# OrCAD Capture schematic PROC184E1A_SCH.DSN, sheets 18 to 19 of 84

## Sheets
18 18. SOC MCU & MAIN GEN IO, OSC: size C; title: SOC MCU & MAIN GENERAL; company: TEXAS INSTRUMENTS INCORPORATED; note: PROC184_SCH
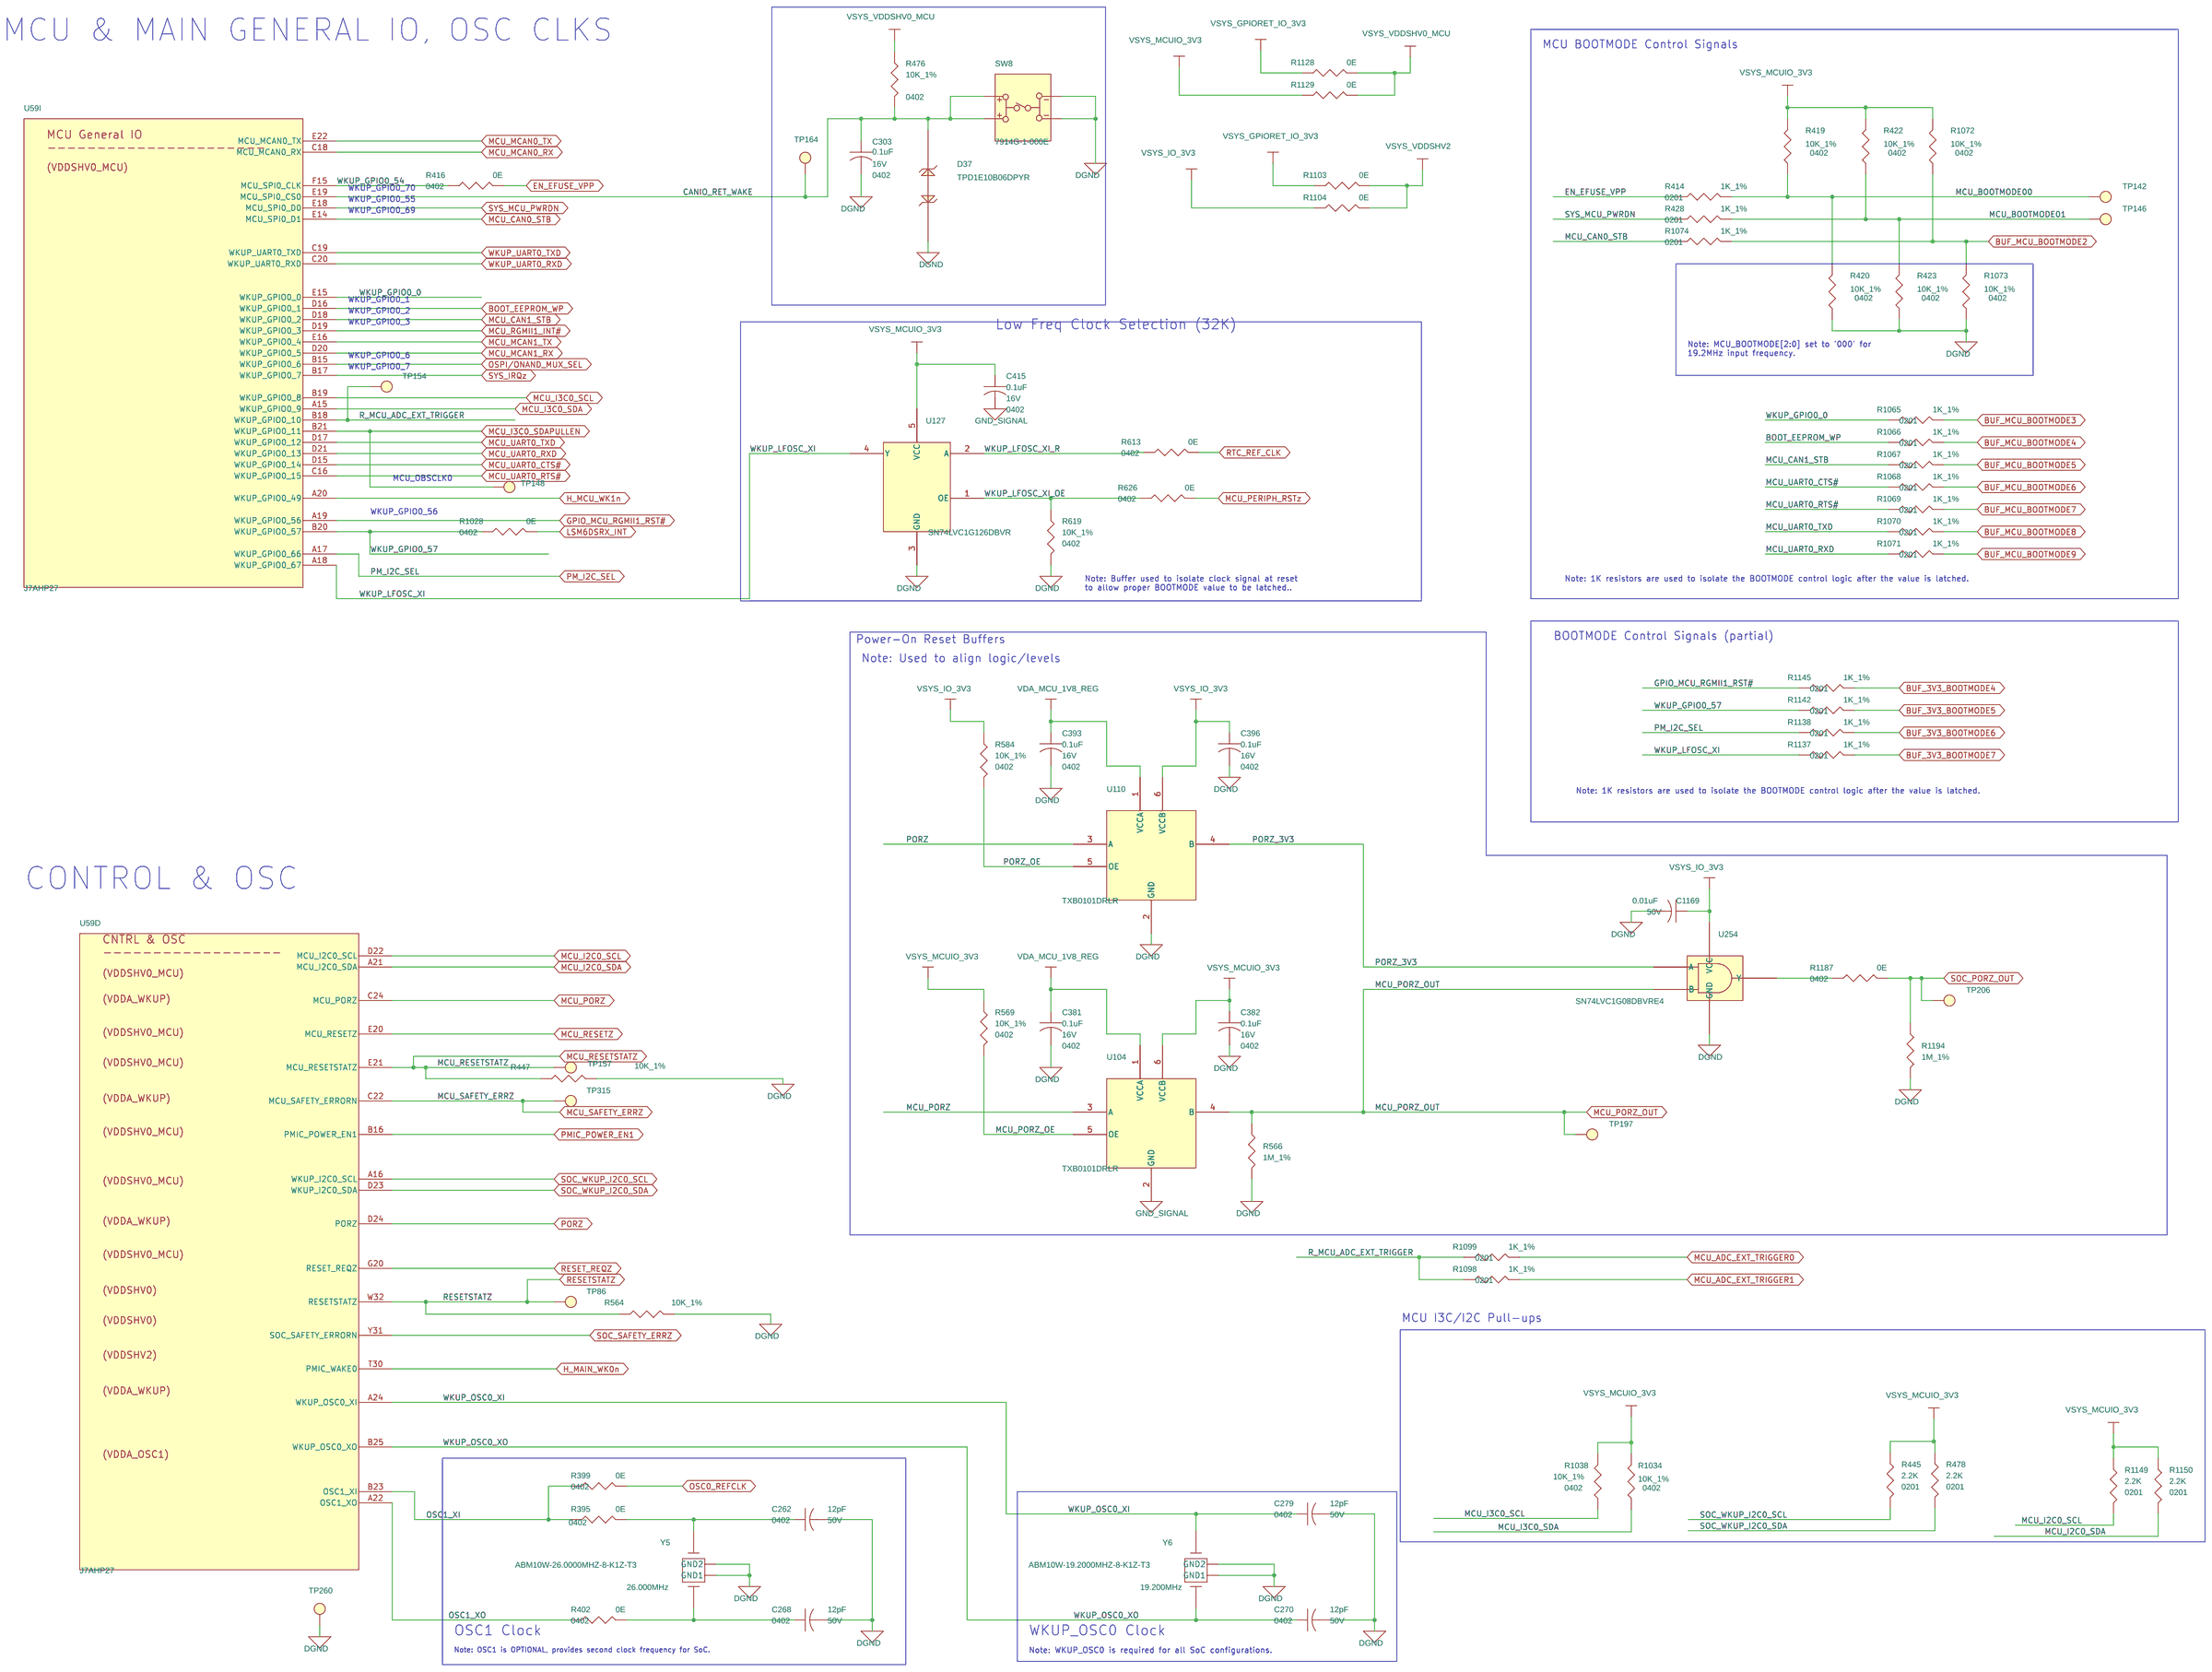
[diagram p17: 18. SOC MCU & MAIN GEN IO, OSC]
19 19. GENERAL: size C; title: GENERAL IO; company: TEXAS INSTRUMENTS INCORPORATED; note: PROC184_SCH
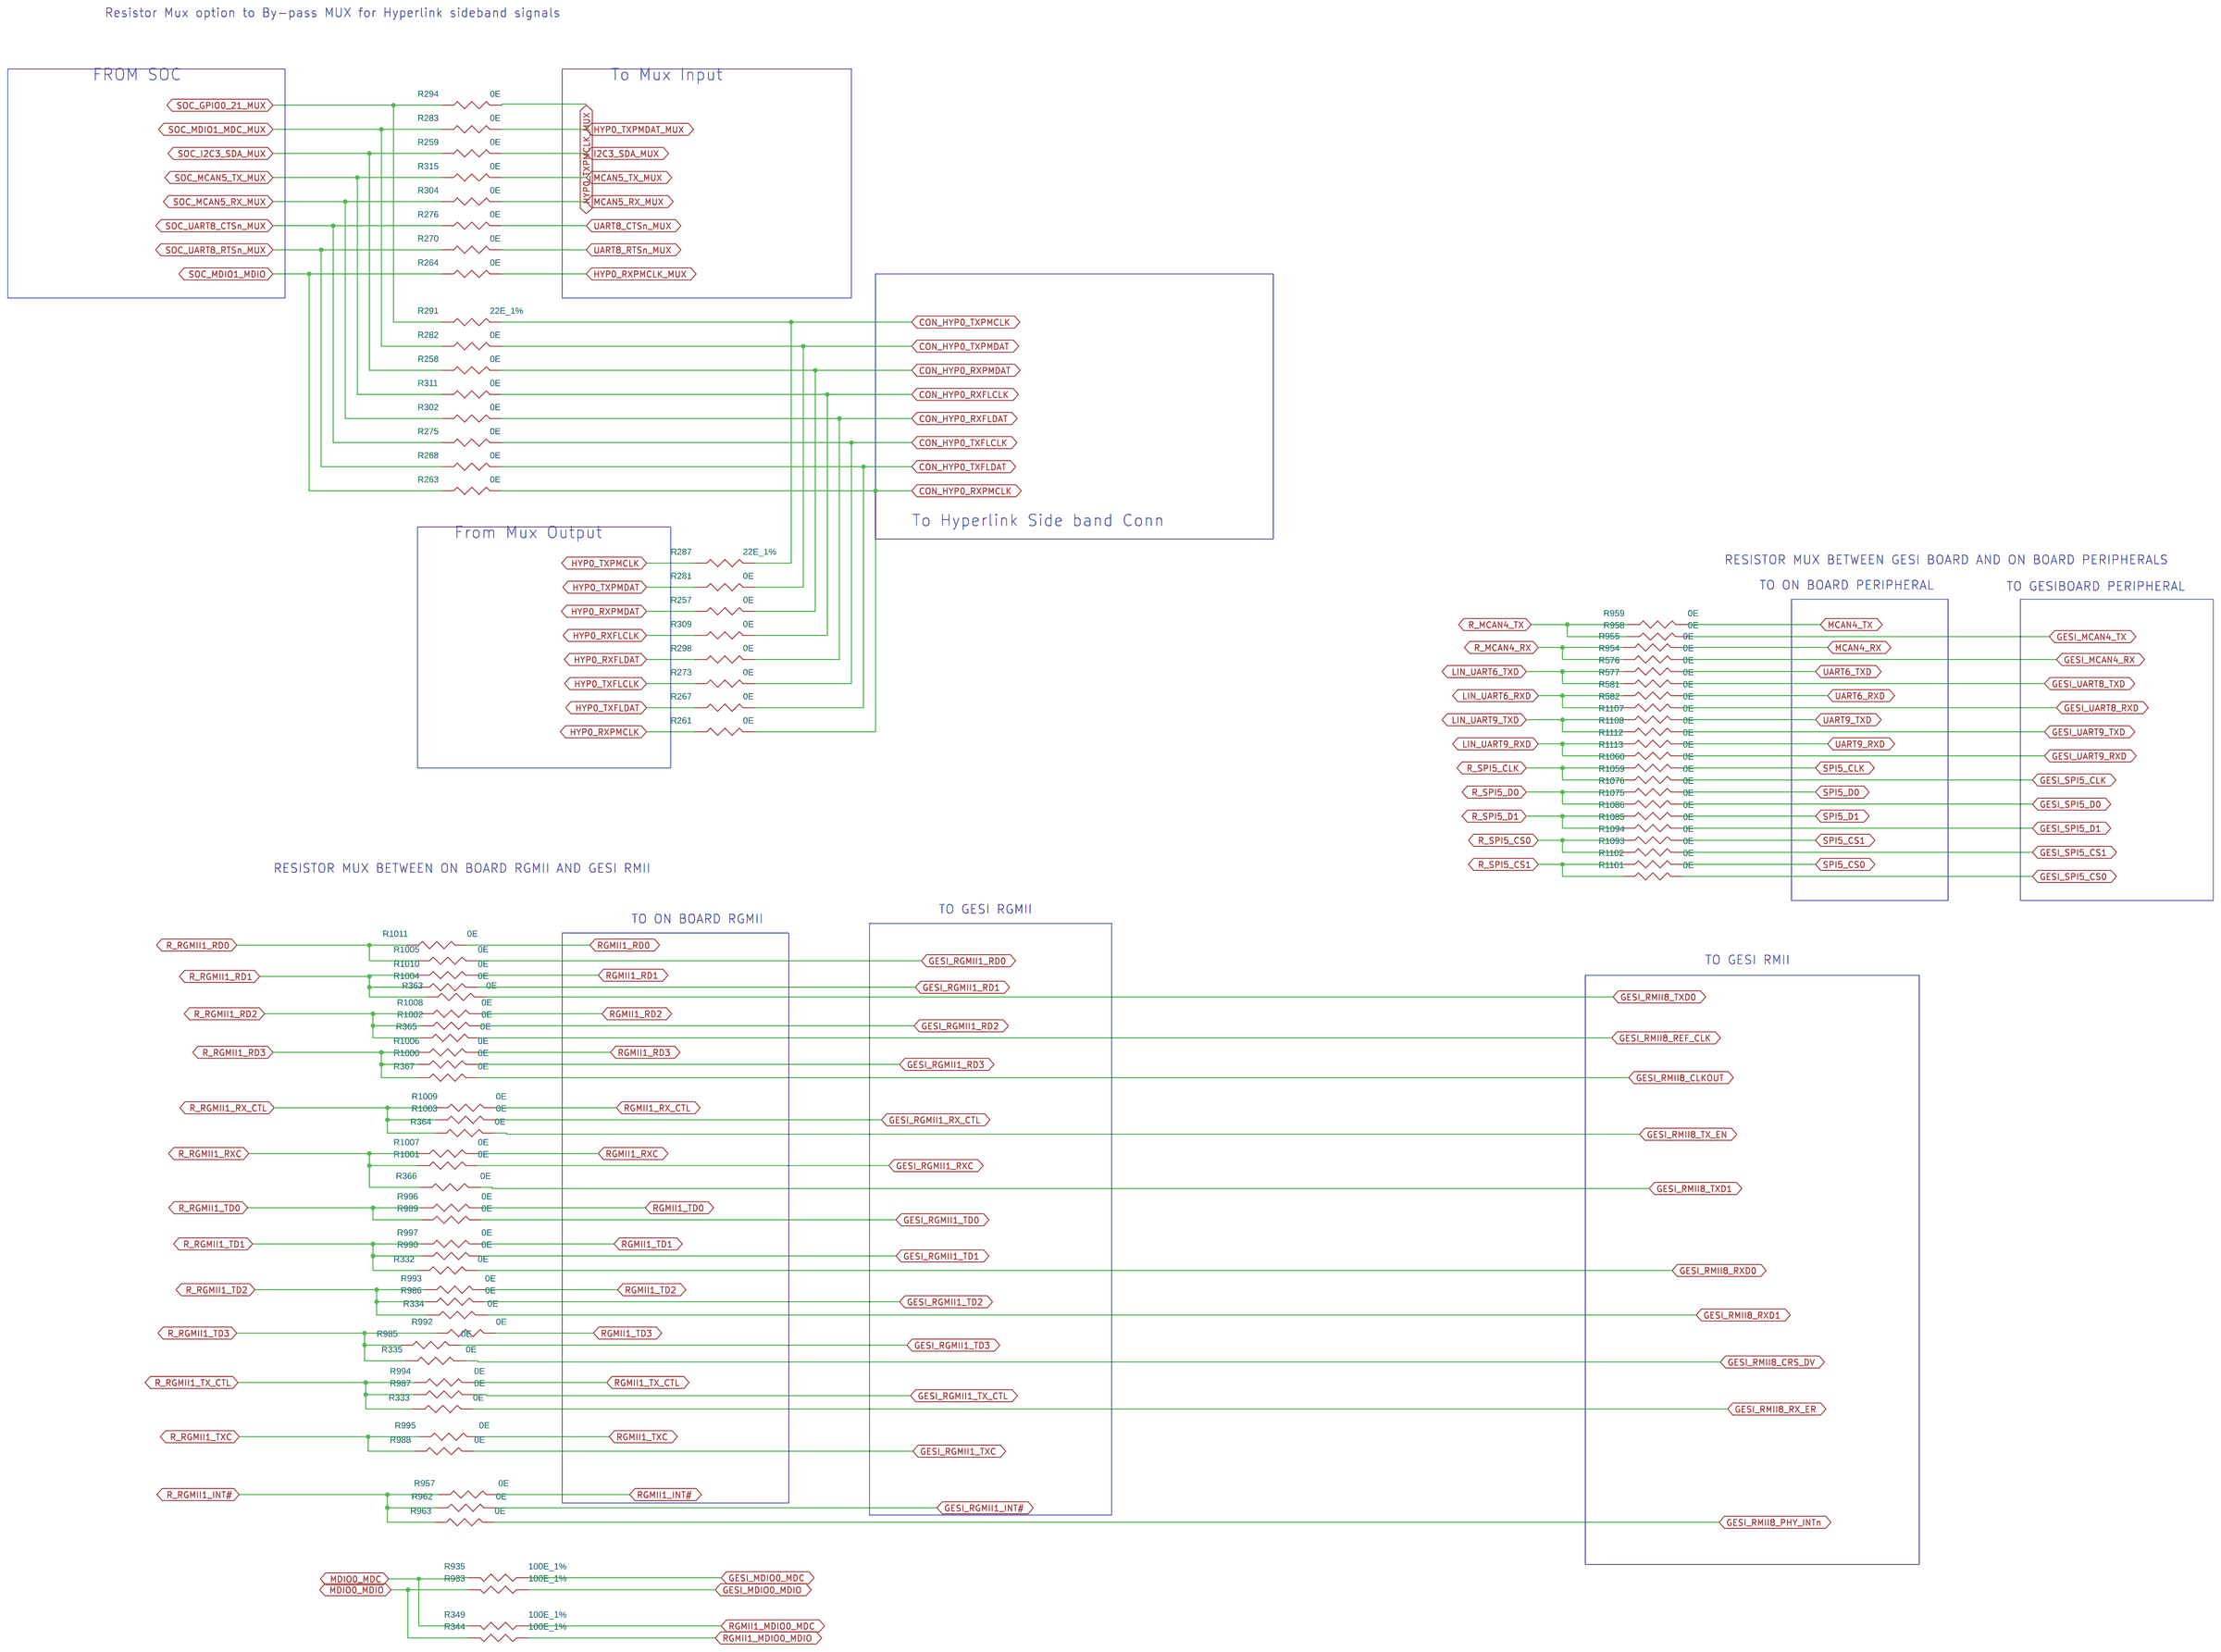
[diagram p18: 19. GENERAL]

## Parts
sheet 15. SOC EMIF1 & LPDDR4
U59  J7AHP27  [BGASKT-33X33-1063-P8MM]  (sections A,B,C,D,E,F,G,H,I,J,K,L,M,N,O,P,Q,R,S,T,U,V,W)
sheet 18. SOC MCU & MAIN GEN IO, OSC
C262  12pF  [CAP0402_0-75]
C268  12pF  [CAP0402_0-75]
C270  12pF  [CAP0402_0-75]
C279  12pF  [CAP0402_0-75]
C303  0.1uF  [CAP0402_0-75]
C381  0.1uF  [CAP0402_0-75]
C382  0.1uF  [CAP0402_0-75]
C393  0.1uF  [CAP0402_0-75]
C396  0.1uF  [CAP0402_0-75]
C415  0.1uF  [CAP0402_0-75]
C1169  0.01uF  [CAP0402_0-75]
D37  TPD1E10B06DPYR  [DIO_DFN0402_0-5]
R395  0E  [RES0402_0-5]
R399  0E  [RES0402_0-5]
R402  0E  [RES0402_0-5]
R414  1K_1%  [RES0201_0-5]
R416  0E  [RES0402_0-5]
R419  10K_1%  [RES0402_0-5]
R420  10K_1%  [RES0402_0-5]
R422  10K_1%  [RES0402_0-5]
R423  10K_1%  [RES0402_0-5]
R428  1K_1%  [RES0201_0-5]
R445  2.2K  [RES0201_0-5]
R447  10K_1%  [RES0402_0-5]
R476  10K_1%  [RES0402_0-5]
R478  2.2K  [RES0201_0-5]
R564  10K_1%  [RES0402_0-5]
R566  1M_1%  [RES0402_0-5]
R569  10K_1%  [RES0402_0-5]
R584  10K_1%  [RES0402_0-5]
R613  0E  [RES0402_0-5]
R619  10K_1%  [RES0402_0-5]
R626  0E  [RES0402_0-5]
R1028  0E  [RES0402_0-5]
R1034  10K_1%  [RES0402_0-5]
R1038  10K_1%  [RES0402_0-5]
R1065  1K_1%  [RES0201_0-5]
R1066  1K_1%  [RES0201_0-5]
R1067  1K_1%  [RES0201_0-5]
R1068  1K_1%  [RES0201_0-5]
R1069  1K_1%  [RES0201_0-5]
R1070  1K_1%  [RES0201_0-5]
R1071  1K_1%  [RES0201_0-5]
R1072  10K_1%  [RES0402_0-5]
R1073  10K_1%  [RES0402_0-5]
R1074  1K_1%  [RES0201_0-5]
R1098  1K_1%  [RES0201_0-5]
R1099  1K_1%  [RES0201_0-5]
R1103  0E  [RES0402_0-5]
R1104  0E  [RES0402_0-5]
R1128  0E  [RES0402_0-5]
R1129  0E  [RES0402_0-5]
R1137  1K_1%  [RES0201_0-5]
R1138  1K_1%  [RES0201_0-5]
R1142  1K_1%  [RES0201_0-5]
R1145  1K_1%  [RES0201_0-5]
R1149  2.2K  [RES0201_0-5]
R1150  2.2K  [RES0201_0-5]
R1187  0E  [RES0402_0-5]
R1194  1M_1%  [RES0402_0-5]
SW8  7914G-1-000E  [SW4_100X216_200X200_SMD_4-2]
TP86  TP30_SMD  [TP30_SMD]
TP142  TP30_SMD  [TP30_SMD]
TP146  TP30_SMD  [TP30_SMD]
TP148  TP30_SMD  [TP30_SMD]
TP154  TP30_SMD  [TP30_SMD]
TP157  TP30_SMD  [TP30_SMD]
TP164  TP30_SMD  [TP30_SMD]
TP197  TP30_SMD  [TP30_SMD]
TP206  TP30_SMD  [TP30_SMD]
TP260  TP30_SMD  [TP30_SMD]
TP315  TP30_SMD  [TP30_SMD]
U104  TXB0101DRLR  [SOT563-6_0-6]
U110  TXB0101DRLR  [SOT563-6_0-6]
U127  SN74LVC1G126DBVR  [SOT23-5_1-5]
U254  SN74LVC1G08DBVRE4  [SOT23-5]
Y5  26.000MHz  [XTAL4_ABM10W_100X80_SMD_0-6]
Y6  19.200MHz  [XTAL4_ABM10W_100X80_SMD_0-6]
sheet 19. GENERAL
R257  0E  [RES0201_0-5]
R258  0E  [RES0201_0-5]
R259  0E  [RES0201_0-5]
R261  0E  [RES0201_0-5]
R263  0E  [RES0201_0-5]
R264  0E  [RES0201_0-5]
R267  0E  [RES0201_0-5]
R268  0E  [RES0201_0-5]
R270  0E  [RES0201_0-5]
R273  0E  [RES0201_0-5]
R275  0E  [RES0201_0-5]
R276  0E  [RES0201_0-5]
R281  0E  [RES0201_0-5]
R282  0E  [RES0201_0-5]
R283  0E  [RES0201_0-5]
R287  22E_1%  [RES0402_0-5]
R291  22E_1%  [RES0402_0-5]
R294  0E  [RES0201_0-5]
R298  0E  [RES0201_0-5]
R302  0E  [RES0201_0-5]
R304  0E  [RES0201_0-5]
R309  0E  [RES0201_0-5]
R311  0E  [RES0201_0-5]
R315  0E  [RES0201_0-5]
R332  0E  [RES0201_0-5]
R333  0E  [RES0201_0-5]
R334  0E  [RES0201_0-5]
R335  0E  [RES0201_0-5]
R344  100E_1%  [RES0402_0-5]
R349  100E_1%  [RES0402_0-5]
R363  0E  [RES0201_0-5]
R364  0E  [RES0201_0-5]
R365  0E  [RES0201_0-5]
R366  0E  [RES0201_0-5]
R367  0E  [RES0201_0-5]
R576  0E  [RES0402_0-5]
R577  0E  [RES0402_0-5]
R581  0E  [RES0402_0-5]
R582  0E  [RES0402_0-5]
R933  100E_1%  [RES0402_0-5]
R935  100E_1%  [RES0402_0-5]
R954  0E  [RES0402_0-5]
R955  0E  [RES0402_0-5]
R957  0E  [RES0201_0-5]
R958  0E  [RES0402_0-5]
R959  0E  [RES0402_0-5]
R962  0E  [RES0201_0-5]
R963  0E  [RES0201_0-5]
R985  0E  [RES0201_0-5]
R986  0E  [RES0201_0-5]
R987  0E  [RES0201_0-5]
R988  0E  [RES0201_0-5]
R989  0E  [RES0201_0-5]
R990  0E  [RES0201_0-5]
R992  0E  [RES0201_0-5]
R993  0E  [RES0201_0-5]
R994  0E  [RES0201_0-5]
R995  0E  [RES0201_0-5]
R996  0E  [RES0201_0-5]
R997  0E  [RES0201_0-5]
R1000  0E  [RES0201_0-5]
R1001  0E  [RES0201_0-5]
R1002  0E  [RES0201_0-5]
R1003  0E  [RES0201_0-5]
R1004  0E  [RES0201_0-5]
R1005  0E  [RES0201_0-5]
R1006  0E  [RES0201_0-5]
R1007  0E  [RES0201_0-5]
R1008  0E  [RES0201_0-5]
R1009  0E  [RES0201_0-5]
R1010  0E  [RES0201_0-5]
R1011  0E  [RES0201_0-5]
R1059  0E  [RES0402_0-5]
R1060  0E  [RES0402_0-5]
R1075  0E  [RES0402_0-5]
R1076  0E  [RES0402_0-5]
R1085  0E  [RES0402_0-5]
R1086  0E  [RES0402_0-5]
R1093  0E  [RES0402_0-5]
R1094  0E  [RES0402_0-5]
R1101  0E  [RES0402_0-5]
R1102  0E  [RES0402_0-5]
R1107  0E  [RES0402_0-5]
R1108  0E  [RES0402_0-5]
R1112  0E  [RES0402_0-5]
R1113  0E  [RES0402_0-5]

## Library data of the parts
U59 = J7AHP27SoC_BGA1063: IC J7AHP27 SoC EVM MICROPROCESSOR BGA1063; Chkd/date: PRADEEP/181223; Crtd /date: TAMILARASU/111223; Custom_Duty: 15%; Customs_HS_Code: 85423100; Distributor_name: NA; Distributor_part_number: NA; Footprint Path: Y:\MIS_DATABASE\Library\ALTIUM_TOOL\PCB_FOOTPRINTS\Altium_Footprint_Lib.PcbLib; Height: 3.30MM; Library Path: Y:\MIS_DATABASE\Library\ALTIUM_TOOL\SCHEMATICS_PARTS\MS_MICROPROCESSOR_Library.schlib; Mfr_name: NA; Mistral Part No: 141223120002; Package: BGA1063; Part_type: ICS\DIGITAL\MICROPROCESSOR; Project: J7AHP27_V08 SOC; RoHS: NA; Temperature: NA; Tolerance: NA; Voltage: NA; Wattage: NA; Weight: NA; Datasheet: Y:\MIS_DATABASE\DATASHEETS\ICS\DIGITAL\MICROCONTROLLER\J7AHP27.PDF
C262 C268 C270 C279 = CAP: CAP CERAMIC 12pF 50V 5% C0G(NP0) 0402; Automotive Alternate_mfr_name: TDK; Automotive Alternate_mfr_part_number: CGA2B2C0G1H120J050BA; Chkd/date: SHREESHAIL/281105; Crtd /date: MAZHAR/040505; Custom_Duty: 15%; Customs_HS_Code: 85322990; Direct Alternate_mfr_name: SAMSUNG; Direct Alternate_mfr_part_number: CL05C120JB5NNNC; Distributor_name: DIGIKEY; Distributor_part_number: 478-1071-1-ND; Footprint Path: Y:\MIS_DATABASE\Library\ALTIUM_TOOL\PCB_FOOTPRINTS\Altium_Footprint_Lib.PcbLib; Height: 0.56MM; Library Path: Y:\MIS_DATABASE\Library\ALTIUM_TOOL\SCHEMATICS_PARTS\MS_DISCRETE_Library.schlib; Manufacturer: AVX CORPORATION; Mfr_name: AVX CORPORATION; Mfr_part_number: 04025A120JAT2A; Mistral Part No: 120015110024-R; Package: 0402; Part_type: CAPACITORS\CERAMIC; Project: EPDA_CORE; RoHS: RoHS; Temperature: -55°C+125°C; Tolerance: 5%; Voltage: 50V; Wattage: NA; Weight: 0.65mg; Datasheet: Y:\MIS_DATABASE\DATASHEETS\CAPACITORS\AVX_MLC.PDF
C303 C381 C382 C393 C396 C415 = CAP: CAP CERAMIC 0.1uF 16V 10% X7R AUTO 0402; Automotive Alternate_mfr_name: TDK; Automotive Alternate_mfr_part_number: CGA2B1X7R1C104K050BC; Chkd/date: NAVEED/021014; Crtd /date: VASANTHA/300514; Custom_Duty: 15%; Customs_HS_Code: 85322990; Direct Alternate_mfr_name: MURATA; Direct Alternate_mfr_part_number: GCM155R71C104JA55D; Distributor_name: DIGIKEY; Distributor_part_number: 490-4759-1-ND; Footprint Path: Y:\MIS_DATABASE\Library\ALTIUM_TOOL\PCB_FOOTPRINTS\Altium_Footprint_Lib.PcbLib; Height: 0.55MM; Library Path: Y:\MIS_DATABASE\Library\ALTIUM_TOOL\SCHEMATICS_PARTS\MS_DISCRETE_Library.schlib; Manufacturer: MURATA; Mfr_name: MURATA; Mfr_part_number: GCM155R71C104KA55D; Mistral Part No: 120016070006-R; Package: 0402; Part_type: CAPACITORS\CERAMIC; Project: DCMIST_FPGA_CARD; RoHS: RoHS; Temperature: -55°C+125°C; Tolerance: 10%; Voltage: 16V; Wattage: NA; Weight: 6mg; Datasheet: Y:\MIS_DATABASE\DATASHEETS\CAPACITORS\MURATA-GCM-SER.PDF
C1169 = CAP: CAP CERAMIC 0.01uF 50V 10% X7R 0402; Automotive Alternate_mfr_name: TDK; Automotive Alternate_mfr_part_number: CGA2B3X7R1H103K050BB; Chkd/date: MANIRAJA/280319; Crtd /date: MANIRAJA/280319; Custom_Duty: 15%; Customs_HS_Code: 85322990; Direct Alternate_mfr_name: TDK; Direct Alternate_mfr_part_number: C1005X7R1H103K050BE; Distributor_name: DIGIKEY; Distributor_part_number: 490-4516-1-ND; Footprint Path: Y:\MIS_DATABASE\Library\ALTIUM_TOOL\PCB_FOOTPRINTS\Altium_Footprint_Lib.PcbLib; Height: 0.55MM; Library Path: Y:\MIS_DATABASE\Library\ALTIUM_TOOL\SCHEMATICS_PARTS\MS_DISCRETE_Library.schlib; Manufacturer: MURATA; Mfr_name: MURATA; Mfr_part_number: GRM155R71H103KA88D; Mistral Part No: 120009030025-R; Package: 0402; Part_type: CAPACITORS\CERAMIC; Project: G4_SVGA; RoHS: RoHS; Temperature: -55°C+125°C; Tolerance: 10%; Voltage: 50V; Wattage: NA; Weight: 0.65mg; Datasheet: Y:\MIS_DATABASE\DATASHEETS\CAPACITORS\GRM155R71H103KA88D.PDF
D37 = DIODE_SOD323: DIODE 1CH ESD PROTECTION X1SON2; Chkd/date: MANIRAJA/040420; Crtd /date: VASANTHA/181114; Custom_Duty: 15%; Customs_HS_Code: 85423100; Distributor_name: DIGIKEY; Distributor_part_number: 296-30406-1-ND; Footprint Path: Y:\MIS_DATABASE\Library\ALTIUM_TOOL\PCB_FOOTPRINTS\Altium_Footprint_Lib.PcbLib; Height: 0.45MM; Library Path: Y:\MIS_DATABASE\Library\ALTIUM_TOOL\SCHEMATICS_PARTS\MS_DISCRETE_Library.schlib; Manufacturer: TEXAS INSTRUMENTS; Mfr_name: TEXAS INSTRUMENTS; Mistral Part No: 130014110022-R; Package: X1SON2; Part_type: DIODE; Project: GALILEO_EVM; RoHS: RoHS; Temperature: -40°C+125°C; Tolerance: NA; Voltage: NA; Wattage: NA; Weight: 1mg; Datasheet: Y:\MIS_DATABASE\DATASHEETS\ICS\INTERFACE\TPD1E10B06-SER.PDF
R395 R399 R402 R576 R577 R581 R582 R626 R954 R955 R958 R959 R1028 R1059 R1060 R1075 R1076 R1085 R1086 R1093 R1094 R1101-R1104 R1107 R1108 R1112 R1113 R1128 R1129 = RESISTOR: RES 0E 1/10W JUMPER 0402; Chkd/date: VASANTHA/061216; Crtd /date: NAVEED/201014; Custom_Duty: 15%; Customs_HS_Code: 85332119; Distributor_name: DIGIKEY; Distributor_part_number: P0.0JCT-ND; Footprint Path: Y:\MIS_DATABASE\Library\ALTIUM_TOOL\PCB_FOOTPRINTS\Altium_Footprint_Lib.PcbLib; Height: 0.40MM; IBISSP_MODLES: VALUE REPEATING 2 TIME; Library Path: Y:\MIS_DATABASE\Library\ALTIUM_TOOL\SCHEMATICS_PARTS\MS_DISCRETE_Library.schlib; Manufacturer: PANASONIC-ECG; Mfr_name: PANASONIC-ECG; Mfr_part_number: ERJ-2GE0R00X; Mistral Part No: 110018030052-R; Package: 0402; Part_type: RESISTORS\FIXED; Project: AEGIS POM; RoHS: RoHS; Temperature: -55°C+155°C; Tolerance: NA; Voltage: NA; Wattage: 1/10W; Weight: 0.8mg; Datasheet: Y:\MIS_DATABASE\DATASHEETS\RESISTORS\PAN-ERJSER_NOV17.PDF
R414 R428 R1065-R1071 R1074 R1098 R1099 R1137 R1138 R1142 R1145 = RESISTOR: RES 1K 1/20W 1% 0201; Chkd/date: RAGESH/120511; Crtd /date: MAZHAR/100511; Custom_Duty: 15%; Customs_HS_Code: 85332119; Distributor_name: MOUSER; Distributor_part_number: 660-RK73H1HTTC1001F; Footprint Path: Y:\MIS_DATABASE\Library\ALTIUM_TOOL\PCB_FOOTPRINTS\Altium_Footprint_Lib.PcbLib; Height: 0.26MM; Library Path: Y:\MIS_DATABASE\Library\ALTIUM_TOOL\SCHEMATICS_PARTS\MS_DISCRETE_Library.schlib; Manufacturer: KOA SPEER; Mfr_name: KOA SPEER; Mfr_part_number: RK73H1HTTC1001F; Mistral Part No: 110015080014-R; Package: 0201; Part_type: RESISTORS\FIXED; Project: HMC; RoHS: RoHS; Temperature: -55°C+155°C; Tolerance: 1%; Voltage: NA; Wattage: 1/20W; Weight: 0.17mg; Datasheet: Y:\MIS_DATABASE\DATASHEETS\RESISTORS\RK73H-SER.PDF
R416 R613 R1187 = RESISTOR: RES 0E 1/10W JUMPER 0402; Assembly_Instruction: DNI; Chkd/date: VASANTHA/061216; Crtd /date: NAVEED/201014; Custom_Duty: 15%; Customs_HS_Code: 85332119; Distributor_name: DIGIKEY; Distributor_part_number: P0.0JCT-ND; Footprint Path: Y:\MIS_DATABASE\Library\ALTIUM_TOOL\PCB_FOOTPRINTS\Altium_Footprint_Lib.PcbLib; Height: 0.40MM; IBISSP_MODLES: VALUE REPEATING 2 TIME; Library Path: Y:\MIS_DATABASE\Library\ALTIUM_TOOL\SCHEMATICS_PARTS\MS_DISCRETE_Library.schlib; Manufacturer: PANASONIC-ECG; Mfr_name: PANASONIC-ECG; Mfr_part_number: ERJ-2GE0R00X; Mistral Part No: 110018030052-R; Package: 0402; Part_type: RESISTORS\FIXED; Project: AEGIS POM; RoHS: RoHS; Temperature: -55°C+155°C; Tolerance: NA; Voltage: NA; Wattage: 1/10W; Weight: 0.8mg; Datasheet: Y:\MIS_DATABASE\DATASHEETS\RESISTORS\PAN-ERJSER_NOV17.PDF
R419 R422 R476 R1034 R1038 R1072 = RESISTOR: RES 10K 1/16W 1% 0402; Assembly_Instruction: DNI; Chkd/date: VASANTHA/201216; Crtd /date: GEETHA/290506; Custom_Duty: 15%; Customs_HS_Code: 85332119; Distributor_name: DIGIKEY; Distributor_part_number: 311-10.0KLRTR-ND; Footprint Path: Y:\MIS_DATABASE\Library\ALTIUM_TOOL\PCB_FOOTPRINTS\Altium_Footprint_Lib.PcbLib; Height: 0.40MM; Library Path: Y:\MIS_DATABASE\Library\ALTIUM_TOOL\SCHEMATICS_PARTS\MS_DISCRETE_Library.schlib; Manufacturer: YAGEO AMERICA; Mfr_name: YAGEO AMERICA; Mfr_part_number: RC0402FR-0710KL; Mistral Part No: 110015090015-R; Package: 0402; Part_type: RESISTORS\FIXED; Project: VOCERA; RoHS: RoHS; Temperature: -55°C+155°C; Tolerance: 1%; Voltage: NA; Wattage: 1/16W; Weight: 0.65mg; Datasheet: Y:\MIS_DATABASE\DATASHEETS\RESISTORS\RCXXXXL-SER_MAR18.PDF
R420 R423 R447 R564 R569 R584 R619 R1073 = RESISTOR: RES 10K 1/16W 1% 0402; Chkd/date: VASANTHA/201216; Crtd /date: GEETHA/290506; Custom_Duty: 15%; Customs_HS_Code: 85332119; Distributor_name: DIGIKEY; Distributor_part_number: 311-10.0KLRTR-ND; Footprint Path: Y:\MIS_DATABASE\Library\ALTIUM_TOOL\PCB_FOOTPRINTS\Altium_Footprint_Lib.PcbLib; Height: 0.40MM; Library Path: Y:\MIS_DATABASE\Library\ALTIUM_TOOL\SCHEMATICS_PARTS\MS_DISCRETE_Library.schlib; Manufacturer: YAGEO AMERICA; Mfr_name: YAGEO AMERICA; Mfr_part_number: RC0402FR-0710KL; Mistral Part No: 110015090015-R; Package: 0402; Part_type: RESISTORS\FIXED; Project: VOCERA; RoHS: RoHS; Temperature: -55°C+155°C; Tolerance: 1%; Voltage: NA; Wattage: 1/16W; Weight: 0.65mg; Datasheet: Y:\MIS_DATABASE\DATASHEETS\RESISTORS\RCXXXXL-SER_MAR18.PDF
R445 R478 R1149 R1150 = RESISTOR: RES 2.2K 1/20W 5% 0201; Chkd/date: MANIRAJA/050517; Crtd /date: MANIRAJA/050517; Custom_Duty: 15%; Customs_HS_Code: 85332119; Distributor_name: DIGIKEY; Distributor_part_number: 311-2.2KNCT-ND; Footprint Path: Y:\MIS_DATABASE\Library\ALTIUM_TOOL\PCB_FOOTPRINTS\Altium_Footprint_Lib.PcbLib; Height: 0.26MM; Library Path: Y:\MIS_DATABASE\Library\ALTIUM_TOOL\SCHEMATICS_PARTS\MS_DISCRETE_Library.schlib; Manufacturer: YAGEO AMERICA; Mfr_name: YAGEO AMERICA; Mfr_part_number: RC0201JR-072K2L; Mistral Part No: 110009030427-R; Package: 0201; Part_type: RESISTORS\FIXED; Project: GOLDEN-I LITE; RoHS: RoHS; Temperature: -55°C+125°C; Tolerance: 5%; Voltage: NA; Wattage: 1/20W; Weight: 0.17mg; Datasheet: Y:\MIS_DATABASE\DATASHEETS\RESISTORS\RCXXXXL-SER_MAR18.PDF
R566 R1194 = RESISTOR: RES 1M 1/10W 1% 0402; Chkd/date: VASANTHA/291216; Crtd /date: MAZHAR/110210; Custom_Duty: 15%; Customs_HS_Code: 85332119; Distributor_name: DIGIKEY; Distributor_part_number: P1.00MLCT-ND; Footprint Path: Y:\MIS_DATABASE\Library\ALTIUM_TOOL\PCB_FOOTPRINTS\Altium_Footprint_Lib.PcbLib; Height: 0.40MM; Library Path: Y:\MIS_DATABASE\Library\ALTIUM_TOOL\SCHEMATICS_PARTS\MS_DISCRETE_Library.schlib; Manufacturer: PANASONIC-ECG; Mfr_name: PANASONIC-ECG; Mfr_part_number: ERJ-2RKF1004X; Mistral Part No: 110010020012-R; Package: 0402; Part_type: RESISTORS\FIXED; Project: KOPIN_MODULS; RoHS: RoHS; Temperature: -55°C+155°C; Tolerance: 1%; Voltage: NA; Wattage: 1/10W; Weight: 0.8mg; Datasheet: Y:\MIS_DATABASE\DATASHEETS\RESISTORS\PAN-ERJSER_NOV17.PDF
SW8 = 7914G-1-000E__7914G: SWITCH SPST-NO 4MM SQ SMD 7914G; Chkd/date: VASANTHA/271216; Crtd /date: BAVISH/051010; Custom_Duty: 24%; Customs_HS_Code: 85369090; Distributor_name: DIGIKEY; Distributor_part_number: 7914G-000ECT-ND; Height: 4.19MM; Library Ref: 7914G-1-000E _7914G; Manufacturer: BOURNS; Mfr_name: BOURNS; Mistral Part No: 130015110004-R; Package: 7914G; Part_type: ELECTRO-MECHANICAL\SWITCH; Project: AAAUC; RoHS: RoHS; Temperature: -55°C+125°C; Tolerance: NA; Voltage: NA; Wattage: NA; Weight: NA; Datasheet: Y:\MIS_DATABASE\DATASHEETS\ICS\DIGITAL\COMBINATIONAL\7914G-1-000E.PDF
TP86 TP157 TP315 = TESTPOINT: TESTPOINT CIR 30 SMD; ASSEMBLY: DNP; Chkd/date: SHREESHAIL/171006; Crtd /date: MAZHAR/171006; Custom_Duty: NA; Customs_HS_Code: NA; Distributor_name: NA; Distributor_part_number: NA; Footprint Path: Y:\MIS_DATABASE\Library\ALTIUM_TOOL\PCB_FOOTPRINTS\Altium_Footprint_Lib.PcbLib; Height: NA; Library Path: Y:\MIS_DATABASE\Library\ALTIUM_TOOL\SCHEMATICS_PARTS\MS_DISCRETE_Library.schlib; MANUFACTURER: LOCAL; MECHANICAL 3D STEP FILE: NA; Mfr_name: LOCAL; Mistral Part No: 130009030930; Package: SMD; Part #: SMT-TP030; Project: BT MODULE_CSRBC04; RoHS: NA; Temperature: NA; Tolerance: NA; Voltage: NA; Wattage: NA; Weight: NA; Datasheet: NA
TP142 TP146 TP148 TP154 TP164 TP197 TP206 TP260 = TESTPOINT: TESTPOINT CIR 30 SMD; Chkd/date: SHREESHAIL/171006; Crtd /date: MAZHAR/171006; Custom_Duty: NA; Customs_HS_Code: NA; Distributor_name: NA; Distributor_part_number: NA; Footprint Path: Y:\MIS_DATABASE\Library\ALTIUM_TOOL\PCB_FOOTPRINTS\Altium_Footprint_Lib.PcbLib; Height: NA; Library Path: Y:\MIS_DATABASE\Library\ALTIUM_TOOL\SCHEMATICS_PARTS\MS_DISCRETE_Library.schlib; MECHANICAL 3D STEP FILE: NA; Manufacturer: LOCAL; Mfr_name: LOCAL; Mistral Part No: 130009030930; Package: SMD; Project: BT MODULE_CSRBC04; RoHS: NA; Temperature: NA; Tolerance: NA; Voltage: NA; Wattage: NA; Weight: NA; Datasheet: NA
U104 U110 = TXS0101DBVR_SOT23-6: IC 1-BIT BIDIR LEVEL SHIFTING AND VOLTAGE TRANSLATOR WITH AUTO DIRECTION-SENSING SOT563-6; Chkd/date: MANIRAJA/290120; Crtd /date: ALVY/290120; Custom_Duty: 15%; Customs_HS_Code: 85423100; Distributor_name: DIGIKEY; Distributor_part_number: 296-24665-1-ND; Footprint Path: Y:\MIS_DATABASE\Library\ALTIUM_TOOL\PCB_FOOTPRINTS\Altium_Footprint_Lib.PcbLib; Height: 0.60MM; Library Path: Y:\MIS_DATABASE\Library\ALTIUM_TOOL\SCHEMATICS_PARTS\MS_MISCINTERFACE_Library.schlib; Manufacturer: TEXAS INSTRUMENTS; Mfr_name: TEXAS INSTRUMENTS; Mistral Part No: 141020010011-R; Package: SOT563-6; Part_type: ICS\INTERFACE\LEVEL TRANSLATOR; Project: J7VCL_SOM DUAL LEO PMIC; RoHS: RoHS; Temperature: -40°C+85°C; Tolerance: NA; Voltage: NA; Wattage: NA; Weight: 28mg; Datasheet: Y:\MIS_DATABASE\DATASHEETS\ICS\INTERFACE\TXB0101XX.PDF
U127 = SN74LVC1G126DBVR_SOT23-5: IC SINGLE BUS BUFFER GATE WITH 3-STATE O/P SOT23-5; Chkd/date: MANIRAJA/130519; Crtd /date: MAZHAR/301106; Custom_Duty: 15%; Customs_HS_Code: 85423100; Distributor_name: DIGIKEY; Distributor_part_number: 296-11605-1-ND; Footprint Path: Y:\MIS_DATABASE\Library\ALTIUM_TOOL\PCB_FOOTPRINTS\Altium_Footprint_Lib.PcbLib; Height: 1.45MM; Library Path: Y:\MIS_DATABASE\Library\ALTIUM_TOOL\SCHEMATICS_PARTS\MS_GATE_Library.schlib; Manufacturer: TEXAS INSTRUMENTS; Mfr_name: TEXAS INSTRUMENTS; Mistral Part No: 141009030232-R; Package: SOT23-5; Part_type: ICS\DIGITAL\GATES; Project: PMP LCD BOARD; RoHS: RoHS; Temperature: -40°C+125°C; Tolerance: NA; Voltage: NA; Wattage: NA; Weight: 6.3mg; Datasheet: Y:\MIS_DATABASE\DATASHEETS\ICS\DIGITAL\GATES\SN74LVC1G126XXX.PDF
U254 = SN74LVC1G08DBVRE4_SOT23-5: IC SINGLE 2-INPUT POSITIVE AND GATE SOT23-5; Automotive Alternate_mfr_name: TEXAS INSTRUMENTS; Automotive Alternate_mfr_part_number: SN74LVC1G08QDBVRQ1; Chkd/date: SUHAS/221010; Crtd /date: USMAN/151008; Custom_Duty: 15%; Customs_HS_Code: 85423100; Distributor_name: DIGIKEY; Distributor_part_number: SN74LVC1G08DBVRE4-ND; Height: 1.45MM; Manufacturer: TEXAS INSTRUMENTS; Mfr_name: TEXAS INSTRUMENTS; Mistral Part No: 141009060026-R; Part_type: ICS\DIGITAL\GATES; Project: KHAN_MAIN; RoHS: Sb/ Br FREE; Temperature: -40°C+85°C; Datasheet: Y:\MIS_DATABASE\DATASHEETS\ICS\DIGITAL\GATES\SN74LVC1G08.PDF
Y5 = CRY4_ABM8G: CRY 26.000MHz 8pF SMD; Chkd/date: ALVY/160421; Crtd /date: MANIRAJA/160421; Custom_Duty: 24%; Customs_HS_Code: 85439000; Distributor_name: DIGIKEY; Distributor_part_number: ABM10W-26.0000MHZ-8-K1Z-T3-ND; Footprint Path: Y:\MIS_DATABASE\Library\ALTIUM_TOOL\PCB_FOOTPRINTS\Altium_Footprint_Lib.PcbLib; Height: 0.60MM; Library Path: Y:\MIS_DATABASE\Library\ALTIUM_TOOL\SCHEMATICS_PARTS\MS_DISCRETE_Library.schlib; Manufacturer: ABRACON CORPORATION; Mfr_name: ABRACON CORPORATION; Mfr_part_number: ABM10W-26.0000MHZ-8-K1Z-T3; Mistral Part No: 130021040032-R; Package: SMD; Part_type: CRYSTAL; Project: TI_J7AEP_EVM_SOM; RoHS: RoHS; Temperature: -40°C+125°C; Tolerance: NA; Voltage: NA; Wattage: NA; Weight: NA; Datasheet: Y:\MIS_DATABASE\DATASHEETS\MISC\CRY_OSC\ABM10W_JUN20.PDF
Y6 = CRY4_ABM8G: CRY 19.200MHz 8pF SMD; Chkd/date: MANIRAJA/250119; Crtd /date: ALVY/250119; Custom_Duty: 24%; Customs_HS_Code: 85439000; Distributor_name: DIGIKEY; Distributor_part_number: ABM10W-19.2000MHZ-8-K1Z-T3-ND; Footprint Path: Y:\MIS_DATABASE\Library\ALTIUM_TOOL\PCB_FOOTPRINTS\Altium_Footprint_Lib.PcbLib; Height: 0.60MM; Library Path: Y:\MIS_DATABASE\Library\ALTIUM_TOOL\SCHEMATICS_PARTS\MS_DISCRETE_Library.schlib; Manufacturer: ABRACON CORPORATION; Mfr_name: ABRACON CORPORATION; Mfr_part_number: ABM10W-19.2000MHZ-8-K1Z-T3; Mistral Part No: 130019010009-R; Package: SMD; Part_type: CRYSTAL; Project: TI_J7_SVB-DUT; RoHS: RoHS; Temperature: -40°C+125°C; Tolerance: NA; Voltage: NA; Wattage: NA; Weight: NA; Datasheet: Y:\MIS_DATABASE\DATASHEETS\MISC\CRY_OSC\ABM10W.PDF
R257-R259 R261 R263 R264 R267 R268 R270 R273 R275 R276 R281-R283 R294 R298 R302 R304 R309 R311 R315 R332-R335 R363-R367 R957 R962 R963 R985-R990 R992-R997 R1000-R1011 = RESISTOR: RES 0E 1/20W 5% 0201; Chkd/date: NAVEED/301214; Crtd /date: MUDDU/120710; Custom_Duty: 15%; Customs_HS_Code: 85332119; Distributor_name: DIGIKEY; Distributor_part_number: 311-0.0NCT-ND; Footprint Path: Y:\MIS_DATABASE\Library\ALTIUM_TOOL\PCB_FOOTPRINTS\Altium_Footprint_Lib.PcbLib; Height: 0.26MM; Library Path: Y:\MIS_DATABASE\Library\ALTIUM_TOOL\SCHEMATICS_PARTS\MS_DISCRETE_Library.schlib; Manufacturer: YAGEO AMERICA; Mfr_name: YAGEO AMERICA; Mfr_part_number: RC0201JR-070RL; Mistral Part No: 110010070067-R; Package: 0201; Part_type: RESISTORS\FIXED; Project: PB_BUGBASE; RoHS: RoHS; Temperature: -55°C+125°C; Tolerance: 5%; Voltage: NA; Wattage: 1/20W; Weight: 0.17mg; Datasheet: Y:\MIS_DATABASE\DATASHEETS\RESISTORS\RCXXXXL-SER_MAR18.PDF
R287 R291 = RESISTOR: RES 22E 1/16W 1% 0402; Chkd/date: SUHAS/290910; Crtd /date: MAZHAR/090909; Cust_part_number: 4700-80047E; Custom_Duty: 15%; Customs_HS_Code: 85332119; Distributor_name: DIGIKEY; Distributor_part_number: 311-22.0LRCT-ND; Footprint Path: Y:\MIS_DATABASE\Library\ALTIUM_TOOL\PCB_FOOTPRINTS\Altium_Footprint_Lib.PcbLib; Height: 0.40MM; Library Path: Y:\MIS_DATABASE\Library\ALTIUM_TOOL\SCHEMATICS_PARTS\MS_DISCRETE_Library.schlib; Manufacturer: YAGEO AMERICA; Mfr_name: YAGEO AMERICA; Mfr_part_number: RC0402FR-0722RL; Mistral Part No: 110009090004-R; Package: 0402; Part_type: RESISTORS\FIXED; Project: VMEFMCD; RoHS: RoHS; Temperature: -55°C+155°C; Tolerance: 1%; Voltage: NA; Wattage: 1/16W; Weight: 0.65mg; Datasheet: Y:\MIS_DATABASE\DATASHEETS\RESISTORS\RCXXXXL-SER_MAR18.PDF
R344 R349 R933 R935 = RESISTOR: RES 100E 1/10W 1% 0402; Assembly_Instruction: DNI; Chkd/date: MANIRAJA/130617; Crtd /date: JEBRAN/040715; Custom_Duty: 15%; Customs_HS_Code: 85332119; Distributor_name: DIGIKEY; Distributor_part_number: P100LCT-ND; Footprint Path: Y:\MIS_DATABASE\Library\ALTIUM_TOOL\PCB_FOOTPRINTS\Altium_Footprint_Lib.PcbLib; Height: 0.40MM; Library Path: Y:\MIS_DATABASE\Library\ALTIUM_TOOL\SCHEMATICS_PARTS\MS_DISCRETE_Library.schlib; Manufacturer: PANASONIC-ECG; Mfr_name: PANASONIC-ECG; Mfr_part_number: ERJ-2RKF1000X; Mistral Part No: 110018020036-R; Package: 0402; Part_type: RESISTORS\FIXED; Project: CYPHY_FVB; RoHS: RoHS; Temperature: -55°C+155°C; Tolerance: 1%; Voltage: NA; Wattage: 1/10W; Weight: 0.8mg; Datasheet: Y:\MIS_DATABASE\DATASHEETS\RESISTORS\PAN-ERJSER_NOV17.PDF

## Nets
DGND: C262.2 C268.2 C270.2 C279.2 C303.2 C381.2 C382.2 C393.2 C396.2 C415.2 C1169.2 D37.1 R420.1 R423.1 R447.2 R564.2 R566.2 R619.2 R1073.1 R1194.2 SW8.1 SW8.4 TP260.1(TP) U104.2(GND) U110.2(GND) U127.3(GND) U254.3(GND) Y5.2(GND1) Y5.4(GND2) Y6.2(GND1) Y6.4(GND2) ; also on sheet 11 12 13 14 15 16 17 20 21 22 23 24 25 26 27 28 29 30 31 32 33 34 35 36 37 38 39 40 41 42 43 44 45 46 47 48 49 50 51 52 53 54 55 56 57 58 59 60 61 62 63 64 65 66 67 68 69 70 71 72 73 76 77 78 79 81 82 83 84
BOOT_EEPROM_WP: R1066.1 U59.D16(WKUP_GPIO0_1) ; also on sheet 43
BUF_3V3_BOOTMODE4: R1145.2 ; also on sheet 62
BUF_3V3_BOOTMODE5: R1142.2 ; also on sheet 62
BUF_3V3_BOOTMODE6: R1138.2 ; also on sheet 62
BUF_3V3_BOOTMODE7: R1137.2 ; also on sheet 62
BUF_MCU_BOOTMODE2: R1072.1 R1073.2 R1074.2 ; also on sheet 62
BUF_MCU_BOOTMODE3: R1065.2 ; also on sheet 62
BUF_MCU_BOOTMODE4: R1066.2 ; also on sheet 62
BUF_MCU_BOOTMODE5: R1067.2 ; also on sheet 62
BUF_MCU_BOOTMODE6: R1068.2 ; also on sheet 62
BUF_MCU_BOOTMODE7: R1069.2 ; also on sheet 62
BUF_MCU_BOOTMODE8: R1070.2 ; also on sheet 62
BUF_MCU_BOOTMODE9: R1071.2 ; also on sheet 62
CANIO_RET_WAKE: C303.1 D37.2 R476.2 SW8.2 SW8.3 TP164.1(TP) U59.E19(MCU_SPI0_CS0)
CON_HYP0_RXFLCLK: R309.2 R311.2 ; also on sheet 29
CON_HYP0_RXFLDAT: R298.2 R302.2 ; also on sheet 29
CON_HYP0_RXPMCLK: R261.2 R263.2 ; also on sheet 29
CON_HYP0_RXPMDAT: R257.2 R258.2 ; also on sheet 29
CON_HYP0_TXFLCLK: R273.2 R275.2 ; also on sheet 29
CON_HYP0_TXFLDAT: R267.2 R268.2 ; also on sheet 29
CON_HYP0_TXPMCLK: R287.2 R291.2 ; also on sheet 29
CON_HYP0_TXPMDAT: R281.2 R282.2 ; also on sheet 29
EN_EFUSE_VPP: R414.1 R416.2 ; also on sheet 72
GESI_MCAN4_RX: R954.2 ; also on sheet 30
GESI_MCAN4_TX: R958.2 ; also on sheet 30
GESI_MDIO0_MDC: R935.1 ; also on sheet 30
GESI_MDIO0_MDIO: R933.1 ; also on sheet 30
GESI_RGMII1_INT#: R962.2 ; also on sheet 30
GESI_RGMII1_RD0: R1005.2 ; also on sheet 30
GESI_RGMII1_RD1: R1004.2 ; also on sheet 30
GESI_RGMII1_RD2: R1002.2 ; also on sheet 30
GESI_RGMII1_RD3: R1000.2 ; also on sheet 30
GESI_RGMII1_RX_CTL: R1003.2 ; also on sheet 30
GESI_RGMII1_RXC: R1001.2 ; also on sheet 30
GESI_RGMII1_TD0: R989.2 ; also on sheet 30
GESI_RGMII1_TD1: R990.2 ; also on sheet 30
GESI_RGMII1_TD2: R986.2 ; also on sheet 30
GESI_RGMII1_TD3: R985.2 ; also on sheet 30
GESI_RGMII1_TX_CTL: R987.2 ; also on sheet 30
GESI_RGMII1_TXC: R988.2 ; also on sheet 30
GESI_RMII8_CLKOUT: R367.2 ; also on sheet 30
GESI_RMII8_CRS_DV: R335.2 ; also on sheet 30
GESI_RMII8_PHY_INTn: R963.2 ; also on sheet 30
GESI_RMII8_REF_CLK: R365.2 ; also on sheet 30
GESI_RMII8_RX_ER: R333.2 ; also on sheet 30
GESI_RMII8_RXD0: R332.2 ; also on sheet 30
GESI_RMII8_RXD1: R334.2 ; also on sheet 30
GESI_RMII8_TX_EN: R364.2 ; also on sheet 30
GESI_RMII8_TXD0: R363.2 ; also on sheet 30
GESI_RMII8_TXD1: R366.2 ; also on sheet 30
GESI_SPI5_CLK: R1059.2 ; also on sheet 30
GESI_SPI5_CS0: R1101.2 ; also on sheet 30
GESI_SPI5_CS1: R1093.2 ; also on sheet 30
GESI_SPI5_D0: R1075.2 ; also on sheet 30
GESI_SPI5_D1: R1085.2 ; also on sheet 30
GESI_UART8_RXD: R582.2 ; also on sheet 30
GESI_UART8_TXD: R577.2 ; also on sheet 30
GESI_UART9_RXD: R1113.2 ; also on sheet 30
GESI_UART9_TXD: R1108.2 ; also on sheet 30
GPIO_MCU_RGMII1_RST#: R1145.1 U59.A19(WKUP_GPIO0_56) ; also on sheet 55
H_MAIN_WK0n: U59.T30(PMIC_WAKE0) ; also on sheet 69
H_MCU_WK1n: U59.A20(WKUP_GPIO0_49) ; also on sheet 69
HYP0_RXFLCLK: R309.1 ; also on sheet 20
HYP0_RXFLDAT: R298.1 ; also on sheet 20
HYP0_RXPMCLK: R261.1 ; also on sheet 20
HYP0_RXPMCLK_MUX: R264.2 ; also on sheet 20
HYP0_RXPMDAT: R257.1 ; also on sheet 20
HYP0_TXFLCLK: R273.1 ; also on sheet 20
HYP0_TXFLDAT: R267.1 ; also on sheet 20
HYP0_TXPMCLK: R287.1 ; also on sheet 20
HYP0_TXPMCLK_MUX: R294.2 ; also on sheet 20
HYP0_TXPMDAT: R281.1 ; also on sheet 20
HYP0_TXPMDAT_MUX: R283.2 ; also on sheet 20
I2C3_SDA_MUX: R259.2 ; also on sheet 20
LIN_UART6_RXD: R581.1 R582.1 ; also on sheet 20
LIN_UART6_TXD: R576.1 R577.1 ; also on sheet 20
LIN_UART9_RXD: R1112.1 R1113.1 ; also on sheet 20
LIN_UART9_TXD: R1107.1 R1108.1 ; also on sheet 20
LSM6DSRX_INT: R1028.2 ; also on sheet 21
MCAN4_RX: R955.2 ; also on sheet 81
MCAN4_TX: R959.2 ; also on sheet 81
MCAN5_RX_MUX: R304.2 ; also on sheet 20
MCAN5_TX_MUX: R315.2 ; also on sheet 20
MCU_ADC_EXT_TRIGGER0: R1099.2 ; also on sheet 58
MCU_ADC_EXT_TRIGGER1: R1098.2 ; also on sheet 30
MCU_BOOTMODE00: R414.2 R419.1 R420.2 TP142.1(TP)
MCU_BOOTMODE01: R422.1 R423.2 R428.2 TP146.1(TP)
MCU_CAN0_STB: R1074.1 U59.E14(MCU_SPI0_D1) ; also on sheet 49
MCU_CAN1_STB: R1067.1 U59.D18(WKUP_GPIO0_2) ; also on sheet 49
MCU_I2C0_SCL: R1149.2 U59.D22(MCU_I2C0_SCL) ; also on sheet 43 69
MCU_I2C0_SDA: R1150.2 U59.A21(MCU_I2C0_SDA) ; also on sheet 43 69
MCU_I3C0_SCL: R1038.1 U59.B19(WKUP_GPIO0_8) ; also on sheet 21 58
MCU_I3C0_SDA: R1034.1 U59.A15(WKUP_GPIO0_9) ; also on sheet 21 58
MCU_I3C0_SDAPULLEN: TP148.1(TP) U59.B21(WKUP_GPIO0_11) ; also on sheet 58
MCU_MCAN0_RX: U59.C18(MCU_MCAN0_RX) ; also on sheet 49
MCU_MCAN0_TX: U59.E22(MCU_MCAN0_TX) ; also on sheet 49
MCU_MCAN1_RX: U59.D20(WKUP_GPIO0_5) ; also on sheet 49
MCU_MCAN1_TX: U59.E16(WKUP_GPIO0_4) ; also on sheet 49
MCU_PERIPH_RSTz: R626.2 ; also on sheet 17 37 44 62
MCU_PORZ: U59.C24(MCU_PORZ) U104.3(A) ; also on sheet 36
MCU_PORZ_OE: R569.2 U104.5(OE)
MCU_PORZ_OUT: R566.1 TP197.1(TP) U104.4(B) U254.2(B) ; also on sheet 37 55 69
MCU_RESETSTATZ: R447.1 TP157.1(TP) U59.E21(MCU_RESETSTATZ) ; also on sheet 37
MCU_RESETZ: U59.E20(MCU_RESETZ) ; also on sheet 36
MCU_RGMII1_INT#: U59.D19(WKUP_GPIO0_3) ; also on sheet 55
MCU_SAFETY_ERRZ: TP315.1(TP) U59.C22(MCU_SAFETY_ERRORN) ; also on sheet 69
MCU_UART0_CTS#: R1068.1 U59.D15(WKUP_GPIO0_14) ; also on sheet 44
MCU_UART0_RTS#: R1069.1 U59.C16(WKUP_GPIO0_15) ; also on sheet 44
MCU_UART0_RXD: R1071.1 U59.D21(WKUP_GPIO0_13) ; also on sheet 44
MCU_UART0_TXD: R1070.1 U59.D17(WKUP_GPIO0_12) ; also on sheet 44
MDIO0_MDC: R349.2 R935.2 ; also on sheet 20
MDIO0_MDIO: R344.2 R933.2 ; also on sheet 20
OSC0_REFCLK: R399.2 ; also on sheet 34
OSC1_XI: R395.1 R399.1 U59.B23(OSC1_XI)
OSC1_XO: R402.1 U59.A22(OSC1_XO)
OSPI/ONAND_MUX_SEL: U59.B15(WKUP_GPIO0_6) ; also on sheet 16 35
PM_I2C_SEL: R1138.1 U59.A17(WKUP_GPIO0_66) ; also on sheet 63
PMIC_POWER_EN1: U59.B16(PMIC_POWER_EN1) ; also on sheet 69
PORZ: U59.D24(PORZ) U110.3(A) ; also on sheet 36
PORZ_3V3: U110.4(B) U254.1(A)
PORZ_OE: R584.2 U110.5(OE)
R_MCAN4_RX: R954.1 R955.1 ; also on sheet 20
R_MCAN4_TX: R958.1 R959.1 ; also on sheet 20
R_MCU_ADC_EXT_TRIGGER: R1098.1 R1099.1 TP154.1(TP) U59.B18(WKUP_GPIO0_10)
R_RGMII1_INT#: R957.1 R962.1 R963.1 ; also on sheet 20
R_RGMII1_RD0: R1005.1 R1011.1 ; also on sheet 20
R_RGMII1_RD1: R363.1 R1004.1 R1010.1 ; also on sheet 20
R_RGMII1_RD2: R365.1 R1002.1 R1008.1 ; also on sheet 20
R_RGMII1_RD3: R367.1 R1000.1 R1006.1 ; also on sheet 20
R_RGMII1_RX_CTL: R364.1 R1003.1 R1009.1 ; also on sheet 20
R_RGMII1_RXC: R366.1 R1001.1 R1007.1 ; also on sheet 20
R_RGMII1_TD0: R989.1 R996.1 ; also on sheet 20
R_RGMII1_TD1: R332.1 R990.1 R997.1 ; also on sheet 20
R_RGMII1_TD2: R334.1 R986.1 R993.1 ; also on sheet 20
R_RGMII1_TD3: R335.1 R985.1 R992.1 ; also on sheet 20
R_RGMII1_TX_CTL: R333.1 R987.1 R994.1 ; also on sheet 20
R_RGMII1_TXC: R988.1 R995.1 ; also on sheet 20
R_SPI5_CLK: R1059.1 R1060.1 ; also on sheet 20
R_SPI5_CS0: R1093.1 R1094.1 ; also on sheet 20
R_SPI5_CS1: R1101.1 R1102.1 ; also on sheet 20
R_SPI5_D0: R1075.1 R1076.1 ; also on sheet 20
R_SPI5_D1: R1085.1 R1086.1 ; also on sheet 20
RESET_REQZ: U59.G20(RESET_REQZ) ; also on sheet 36
RESETSTATZ: R564.1 TP86.1(TP) U59.W32(RESETSTATZ) ; also on sheet 30 37 62
RGMII1_INT#: R957.2 ; also on sheet 56
RGMII1_MDIO0_MDC: R349.1 ; also on sheet 56
RGMII1_MDIO0_MDIO: R344.1 ; also on sheet 56
RGMII1_RD0: R1011.2 ; also on sheet 56
RGMII1_RD1: R1010.2 ; also on sheet 56
RGMII1_RD2: R1008.2 ; also on sheet 56
RGMII1_RD3: R1006.2 ; also on sheet 56
RGMII1_RX_CTL: R1009.2 ; also on sheet 56
RGMII1_RXC: R1007.2 ; also on sheet 56
RGMII1_TD0: R996.2 ; also on sheet 56
RGMII1_TD1: R997.2 ; also on sheet 56
RGMII1_TD2: R993.2 ; also on sheet 56
RGMII1_TD3: R992.2 ; also on sheet 56
RGMII1_TX_CTL: R994.2 ; also on sheet 56
RGMII1_TXC: R995.2 ; also on sheet 56
RTC_REF_CLK: R613.2 ; also on sheet 58
SOC_GPIO0_21_MUX: R291.1 R294.1 ; also on sheet 20
SOC_I2C3_SDA_MUX: R258.1 R259.1 ; also on sheet 20
SOC_MCAN5_RX_MUX: R302.1 R304.1 ; also on sheet 20
SOC_MCAN5_TX_MUX: R311.1 R315.1 ; also on sheet 20
SOC_MDIO1_MDC_MUX: R282.1 R283.1 ; also on sheet 20
SOC_MDIO1_MDIO: R263.1 R264.1 ; also on sheet 20
SOC_PORZ_OUT: R1187.2 R1194.1 TP206.1(TP) ; also on sheet 30 32 37 43 51 56 59 60 62 69
SOC_SAFETY_ERRZ: U59.Y31(SOC_SAFETY_ERRORN) ; also on sheet 69
SOC_UART8_CTSn_MUX: R275.1 R276.1 ; also on sheet 20
SOC_UART8_RTSn_MUX: R268.1 R270.1 ; also on sheet 20
SOC_WKUP_I2C0_SCL: R445.2 U59.A16(WKUP_I2C0_SCL) ; also on sheet 23 43
SOC_WKUP_I2C0_SDA: R478.2 U59.D23(WKUP_I2C0_SDA) ; also on sheet 23 43
SPI5_CLK: R1060.2 ; also on sheet 58
SPI5_CS0: R1102.2 ; also on sheet 58
SPI5_CS1: R1094.2 ; also on sheet 58
SPI5_D0: R1076.2 ; also on sheet 58
SPI5_D1: R1086.2 ; also on sheet 58
SYS_IRQz: U59.B17(WKUP_GPIO0_7) ; also on sheet 35
SYS_MCU_PWRDN: R428.1 U59.E18(MCU_SPI0_D0) ; also on sheet 35
UART6_RXD: R581.2 ; also on sheet 46
UART6_TXD: R576.2 ; also on sheet 46
UART8_CTSn_MUX: R276.2 ; also on sheet 20
UART8_RTSn_MUX: R270.2 ; also on sheet 20
UART9_RXD: R1112.2 ; also on sheet 46
UART9_TXD: R1107.2 ; also on sheet 46
VDA_MCU_1V8_REG: C381.1 C393.1 U104.1(VCCA) U110.1(VCCA) ; also on sheet 69 74
VSYS_GPIORET_IO_3V3: R1103.1 R1128.1 ; also on sheet 75
VSYS_IO_3V3: C396.1 C1169.1 R584.1 R1104.1 U110.6(VCCB) U254.5(VCC) ; also on sheet 20 22 24 29 30 31 32 33 35 36 37 38 40 41 42 43 45 46 48 50 51 53 56 57 58 59 60 61 65 66 68 75 81 82
VSYS_MCUIO_3V3: C382.1 C415.1 R419.2 R422.2 R445.1 R478.1 R569.1 R1034.2 R1038.2 R1072.2 R1129.1 R1149.1 R1150.1 U104.6(VCCB) U127.5(VCC) ; also on sheet 16 17 21 22 23 35 36 43 44 48 49 55 62 65 68 75
VSYS_VDDSHV0_MCU: R476.1 R1128.2 R1129.2
VSYS_VDDSHV2: R1103.2 R1104.2 ; also on sheet 20 81
WKUP_GPIO0_0: R1065.1 U59.E15(WKUP_GPIO0_0)
WKUP_GPIO0_54: R416.1 U59.F15(MCU_SPI0_CLK)
WKUP_GPIO0_57: R1028.1 R1142.1 U59.B20(WKUP_GPIO0_57)
WKUP_LFOSC_XI: R1137.1 U59.A18(WKUP_GPIO0_67) U127.4(Y)
WKUP_LFOSC_XI_OE: R619.1 R626.1 U127.1(OE)
WKUP_LFOSC_XI_R: R613.1 U127.2(A)
WKUP_OSC0_XI: C279.1 U59.A24(WKUP_OSC0_XI) Y6.3
WKUP_OSC0_XO: C270.1 U59.B25(WKUP_OSC0_XO) Y6.1
WKUP_UART0_RXD: U59.C20(WKUP_UART0_RXD) ; also on sheet 44
WKUP_UART0_TXD: U59.C19(WKUP_UART0_TXD) ; also on sheet 44
N19376907: C262.1 R395.2 Y5.3
N19376959: C268.1 R402.2 Y5.1
N33181549: R1187.1 U254.4(Y)

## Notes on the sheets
sheet 18
- MCU & MAIN GENERAL IO, OSC CLKS
- MCU BOOTMODE Control Signals
- WKUP_GPIO0_55
- WKUP_GPIO0_70
- WKUP_GPIO0_69
- WKUP_GPIO0_1
- WKUP_GPIO0_2
- WKUP_GPIO0_3
- Low Freq Clock Selection (32K)
- Note: MCU_BOOTMODE[2:0] set to '000' for
  19.2MHz input frequency.
- WKUP_GPIO0_6
- WKUP_GPIO0_7
- MCU_OBSCLK0
- WKUP_GPIO0_56
- Note: Buffer used to isolate clock signal at reset
  to allow proper BOOTMODE value to be latched..
- Note: 1K resistors are used to isolate the BOOTMODE control logic after the value is latched.
- BOOTMODE Control Signals (partial)
- Power-On Reset Buffers
- Note: Used to align logic/levels
- Note: 1K resistors are used to isolate the BOOTMODE control logic after the value is latched.
- CONTROL & OSC
- MCU I3C/I2C Pull-ups
- OSC1 Clock
- WKUP_OSC0 Clock
- Note: OSC1 is OPTIONAL, provides second clock frequency for SoC.
- Note: WKUP_OSC0 is required for all SoC configurations.
sheet 19
- Resistor Mux option to By-pass MUX for Hyperlink sideband signals
- FROM SOC
- To Mux Input
- From Mux Output
- To Hyperlink Side band Conn
- RESISTOR MUX BETWEEN GESI BOARD AND ON BOARD PERIPHERALS
- TO ON BOARD PERIPHERAL
- TO GESIBOARD PERIPHERAL
- RESISTOR MUX BETWEEN ON BOARD RGMII AND GESI RMII
- TO GESI RGMII
- TO ON BOARD RGMII
- TO GESI RMII
